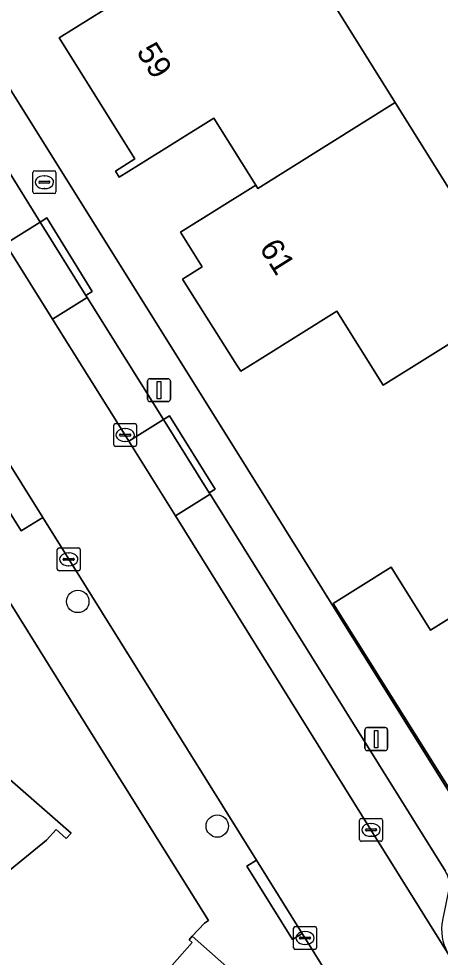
# Model space of a CAD drawing. Extents: x 158835 to 160077, y 386387 to 387778.
# Drawn here: x 159259.68 to 159278.07, y 386903.92 to 386944.89 of the extents above; entities that cross this region are included whole.
import ezdxf

# ---------------------------------------------------------------- set-up
doc = ezdxf.new("R2010")
doc.units = 0
for name, color, linetype in [('IMGEO_Boom', 7, 'Continuous'), ('IMGEO_Brandkraan', 7, 'Continuous'), ('IMGEO_Erf', 7, 'Continuous'), ('IMGEO_Kolk', 7, 'Continuous'), ('IMGEO_Lichtmast', 7, 'Continuous'), ('IMGEO_Muur', 7, 'Continuous'), ('IMGEO_Pand', 7, 'Continuous'), ('IMGEO_Pand_nummerreeks', 7, 'Continuous'), ('IMGEO_Parkeervlak_open', 7, 'Continuous'), ('IMGEO_Rijbaan_lokaal_open', 7, 'Continuous'), ('IMGEO_Voetpad_open', 7, 'Continuous')]:
    doc.layers.add(name, color=color, linetype=linetype)

msp = doc.modelspace()

# ---------------------------------------------------------------- linework, layer by layer
at = {"layer": 'IMGEO_Boom'}
for centre in [(159262.254, 386919.452), (159268.34, 386909.646)]:
    msp.add_circle(centre, 0.489, dxfattribs=at)
at = {"layer": 'IMGEO_Brandkraan'}
for p, q in [((159260.299, 386937.33), (159260.299, 386938.182)), ((159260.374, 386938.256), (159261.226, 386938.256)), ((159260.787, 386938.036), (159260.812, 386938.036)), ((159261.3, 386938.182), (159261.3, 386937.33)), ((159260.558, 386937.75), (159260.558, 386937.762)), ((159260.996, 386937.713), (159260.598, 386937.713)), ((159260.601, 386937.799), (159260.999, 386937.799)), ((159260.81, 386937.476), (159260.785, 386937.476)), ((159261.042, 386937.762), (159261.042, 386937.75)), ((159261.226, 386937.256), (159260.374, 386937.256))]:
    msp.add_line(p, q, dxfattribs=at)
for points in [[(159260.299, 386937.33), (159260.299, 386938.182)], [(159260.374, 386938.256), (159261.226, 386938.256)], [(159261.3, 386938.182), (159261.3, 386937.33)], [(159261.226, 386937.256), (159260.374, 386937.256)]]:
    msp.add_lwpolyline(points, dxfattribs=at)
for centre, radius, start, end in [((159260.376, 386938.18), 0.0765, 91.552, 178.448), ((159260.376, 386938.18), 0.0765, 91.552, 178.448), ((159261.224, 386938.18), 0.0765, 1.552, 88.448), ((159261.224, 386938.18), 0.0765, 1.552, 88.448), ((159260.598, 386937.759), 0.0403, 85.8775, 175.7526), ((159260.595, 386937.749), 0.0366, 178.938, 274.7102), ((159260.999, 386937.756), 0.043, 264.8664, 352.4533), ((159261.003, 386937.761), 0.0386, 1.7309, 96.639), ((159260.376, 386937.332), 0.0765, 181.552, 268.448), ((159260.376, 386937.332), 0.0765, 181.552, 268.448), ((159261.224, 386937.332), 0.0765, 271.552, 358.448), ((159261.224, 386937.332), 0.0765, 271.552, 358.448)]:
    msp.add_arc(centre, radius, start, end, dxfattribs=at)
for centre, major_axis, ratio, start_param, end_param in [((159260.786, 386937.756), (-0.387, 0.002), 0.722429, 4.712389, 7.853982), ((159260.811, 386937.756), (-0.39, 0.002), 0.717154, 1.570796, 4.712389)]:
    msp.add_ellipse(centre, major_axis=major_axis, ratio=ratio, start_param=start_param, end_param=end_param, dxfattribs=at)
at = {"layer": 'IMGEO_Erf'}
for points in [[(159231.551, 386986.255), (159234.22, 386981.98), (159243.007, 386967.906), (159269.667, 386925.206), (159275.29, 386916.2), (159281.43, 386906.366), (159281.531, 386906.228), (159281.643, 386906.1), (159281.767, 386905.982), (159281.9, 386905.876), (159282.043, 386905.783), (159282.193, 386905.702), (159282.35, 386905.635), (159282.513, 386905.582), (159282.682, 386905.544)], [(159270.805, 386949.721), (159276.102, 386941.24), (159281.5, 386932.598), (159275.572, 386928.895), (159273.559, 386932.118), (159270.217, 386930.031), (159269.363, 386929.508), (159269.196, 386929.772), (159266.827, 386933.518), (159267.687, 386934.062), (159266.74, 386935.572), (159270.02, 386937.621), (159268.188, 386940.554), (159264.908, 386938.505), (159264.062, 386937.972), (159263.893, 386938.244), (159264.739, 386938.775), (159261.439, 386944.056), (159264.719, 386946.106)], [(159250.309, 386879.575), (159252.121, 386882.09), (159254.029, 386880.721), (159252.222, 386878.203), (159261.297, 386871.692), (159264.16, 386875.708), (159253.134, 386883.625), (159256.2, 386887.125), (159263.288, 386882.016), (159266.18, 386886.027), (159259.472, 386890.864), (159265.812, 386898.129), (159263.427, 386900.23), (159267.244, 386904.559), (159267.108, 386904.678), (159267.248, 386904.836), (159267.781, 386905.402), (159267.952, 386905.515), (159262.274, 386914.62), (159257.972, 386921.518)], [(159279.018, 386910.377), (159273.393, 386919.361), (159275.926, 386920.947), (159277.645, 386918.202), (159283.167, 386921.647)], [(159245.823, 386903.008), (159243.006, 386905.468), (159246.984, 386910.024), (159249.801, 386907.563), (159251.956, 386910.047), (159249.142, 386912.511), (159253.125, 386917.06), (159261.959, 386909.328), (159261.749, 386909.097), (159261.316, 386909.492), (159260.895, 386909.03), (159258.189, 386906.835), (159254.923, 386903.111)]]:
    msp.add_lwpolyline(points, dxfattribs=at)
at = {"layer": 'IMGEO_Kolk'}
for p, q in [((159263.896, 386927.217), (159264.748, 386927.217)), ((159263.821, 386926.291), (159263.821, 386927.143)), ((159264.309, 386926.997), (159264.334, 386926.997)), ((159264.822, 386927.143), (159264.822, 386926.291)), ((159264.08, 386926.711), (159264.08, 386926.723)), ((159264.518, 386926.674), (159264.12, 386926.674)), ((159264.123, 386926.76), (159264.521, 386926.76)), ((159264.332, 386926.437), (159264.307, 386926.437)), ((159264.564, 386926.723), (159264.564, 386926.711)), ((159264.748, 386926.217), (159263.896, 386926.217)), ((159261.36, 386920.864), (159261.36, 386921.716)), ((159261.435, 386921.79), (159262.287, 386921.79)), ((159261.848, 386921.57), (159261.873, 386921.57)), ((159262.361, 386921.716), (159262.361, 386920.864)), ((159261.619, 386921.284), (159261.619, 386921.296)), ((159262.057, 386921.247), (159261.659, 386921.247)), ((159261.662, 386921.333), (159262.06, 386921.333)), ((159262.103, 386921.296), (159262.103, 386921.284)), ((159262.287, 386920.79), (159261.435, 386920.79)), ((159261.871, 386921.01), (159261.846, 386921.01)), ((159274.55, 386909.052), (159274.55, 386909.904)), ((159274.625, 386909.978), (159275.477, 386909.978)), ((159275.038, 386909.758), (159275.063, 386909.758)), ((159275.551, 386909.904), (159275.551, 386909.052)), ((159274.809, 386909.472), (159274.809, 386909.484)), ((159275.247, 386909.435), (159274.849, 386909.435)), ((159274.852, 386909.521), (159275.25, 386909.521)), ((159275.061, 386909.198), (159275.036, 386909.198)), ((159275.293, 386909.484), (159275.293, 386909.472)), ((159275.477, 386908.978), (159274.625, 386908.978)), ((159271.668, 386904.332), (159271.668, 386905.184)), ((159271.743, 386905.258), (159272.595, 386905.258)), ((159272.669, 386905.184), (159272.669, 386904.332)), ((159271.927, 386904.752), (159271.927, 386904.764)), ((159272.365, 386904.715), (159271.967, 386904.715)), ((159271.97, 386904.801), (159272.368, 386904.801)), ((159272.156, 386905.038), (159272.181, 386905.038)), ((159272.411, 386904.764), (159272.411, 386904.752)), ((159272.179, 386904.478), (159272.154, 386904.478)), ((159272.595, 386904.258), (159271.743, 386904.258))]:
    msp.add_line(p, q, dxfattribs=at)
for points in [[(159263.896, 386927.217), (159264.748, 386927.217)], [(159263.821, 386926.291), (159263.821, 386927.143)], [(159264.822, 386927.143), (159264.822, 386926.291)], [(159264.748, 386926.217), (159263.896, 386926.217)], [(159261.36, 386920.864), (159261.36, 386921.716)], [(159261.435, 386921.79), (159262.287, 386921.79)], [(159262.361, 386921.716), (159262.361, 386920.864)], [(159262.287, 386920.79), (159261.435, 386920.79)], [(159274.55, 386909.052), (159274.55, 386909.904)], [(159274.625, 386909.978), (159275.477, 386909.978)], [(159275.551, 386909.904), (159275.551, 386909.052)], [(159275.477, 386908.978), (159274.625, 386908.978)], [(159271.668, 386904.332), (159271.668, 386905.184)], [(159271.743, 386905.258), (159272.595, 386905.258)], [(159272.669, 386905.184), (159272.669, 386904.332)], [(159272.595, 386904.258), (159271.743, 386904.258)]]:
    msp.add_lwpolyline(points, dxfattribs=at)
for centre, radius, start, end in [((159263.898, 386927.141), 0.0765, 91.552, 178.448), ((159263.898, 386927.141), 0.0765, 91.552, 178.448), ((159264.746, 386927.141), 0.0765, 1.552, 88.448), ((159264.746, 386927.141), 0.0765, 1.552, 88.448), ((159264.12, 386926.72), 0.0403, 85.8775, 175.7526), ((159264.117, 386926.71), 0.0366, 178.938, 274.7102), ((159264.521, 386926.717), 0.043, 264.8664, 352.4533), ((159264.525, 386926.722), 0.0386, 1.7309, 96.639), ((159263.898, 386926.293), 0.0765, 181.552, 268.448), ((159263.898, 386926.293), 0.0765, 181.552, 268.448), ((159264.746, 386926.293), 0.0765, 271.552, 358.448), ((159264.746, 386926.293), 0.0765, 271.552, 358.448), ((159261.437, 386921.714), 0.0765, 91.552, 178.448), ((159261.437, 386921.714), 0.0765, 91.552, 178.448), ((159262.285, 386921.714), 0.0765, 1.552, 88.448), ((159262.285, 386921.714), 0.0765, 1.552, 88.448), ((159261.659, 386921.293), 0.0403, 85.8775, 175.7526), ((159261.656, 386921.283), 0.0366, 178.938, 274.7102), ((159262.06, 386921.29), 0.043, 264.8664, 352.4533), ((159262.064, 386921.295), 0.0386, 1.7309, 96.639), ((159261.437, 386920.866), 0.0765, 181.552, 268.448), ((159261.437, 386920.866), 0.0765, 181.552, 268.448), ((159262.285, 386920.866), 0.0765, 271.552, 358.448), ((159262.285, 386920.866), 0.0765, 271.552, 358.448), ((159274.627, 386909.902), 0.0765, 91.552, 178.448), ((159274.627, 386909.902), 0.0765, 91.552, 178.448), ((159275.475, 386909.902), 0.0765, 1.552, 88.448), ((159275.475, 386909.902), 0.0765, 1.552, 88.448), ((159274.849, 386909.481), 0.0403, 85.8775, 175.7526), ((159274.846, 386909.471), 0.0366, 178.938, 274.7102), ((159275.25, 386909.478), 0.043, 264.8664, 352.4533), ((159275.254, 386909.483), 0.0386, 1.7309, 96.639), ((159274.627, 386909.054), 0.0765, 181.552, 268.448), ((159274.627, 386909.054), 0.0765, 181.552, 268.448), ((159275.475, 386909.054), 0.0765, 271.552, 358.448), ((159275.475, 386909.054), 0.0765, 271.552, 358.448), ((159271.745, 386905.182), 0.0765, 91.552, 178.448), ((159271.745, 386905.182), 0.0765, 91.552, 178.448), ((159272.593, 386905.182), 0.0765, 1.552, 88.448), ((159272.593, 386905.182), 0.0765, 1.552, 88.448), ((159271.967, 386904.761), 0.0403, 85.8775, 175.7526), ((159271.964, 386904.751), 0.0366, 178.938, 274.7102), ((159272.368, 386904.758), 0.043, 264.8664, 352.4533), ((159272.372, 386904.763), 0.0386, 1.7309, 96.639), ((159271.745, 386904.334), 0.0765, 181.552, 268.448), ((159271.745, 386904.334), 0.0765, 181.552, 268.448), ((159272.593, 386904.334), 0.0765, 271.552, 358.448), ((159272.593, 386904.334), 0.0765, 271.552, 358.448)]:
    msp.add_arc(centre, radius, start, end, dxfattribs=at)
for centre, major_axis, ratio, start_param, end_param in [((159264.308, 386926.717), (-0.387, 0.002), 0.722429, 4.712389, 7.853982), ((159264.333, 386926.717), (-0.39, 0.002), 0.717154, 1.570796, 4.712389), ((159261.847, 386921.29), (-0.387, 0.002), 0.722429, 4.712389, 7.853982), ((159261.872, 386921.29), (-0.39, 0.002), 0.717154, 1.570796, 4.712389), ((159275.037, 386909.478), (-0.387, 0.002), 0.722429, 4.712389, 7.853982), ((159275.062, 386909.478), (-0.39, 0.002), 0.717154, 1.570796, 4.712389), ((159272.155, 386904.758), (-0.387, 0.002), 0.722429, 4.712389, 7.853982), ((159272.18, 386904.758), (-0.39, 0.002), 0.717154, 1.570796, 4.712389)]:
    msp.add_ellipse(centre, major_axis=major_axis, ratio=ratio, start_param=start_param, end_param=end_param, dxfattribs=at)
at = {"layer": 'IMGEO_Lichtmast'}
for p, q in [((159265.302, 386928.278), (159265.302, 386929.078)), ((159265.302, 386929.078), (159265.302, 386928.278)), ((159265.402, 386929.178), (159266.192, 386929.178)), ((159266.192, 386929.178), (159265.402, 386929.178)), ((159266.292, 386929.078), (159266.292, 386928.278)), ((159266.292, 386928.278), (159266.292, 386929.078)), ((159266.192, 386928.178), (159265.402, 386928.178)), ((159265.402, 386928.178), (159266.192, 386928.178)), ((159274.781, 386913.042), (159274.781, 386913.842)), ((159274.781, 386913.842), (159274.781, 386913.042)), ((159274.881, 386913.942), (159275.671, 386913.942)), ((159275.671, 386913.942), (159274.881, 386913.942)), ((159275.771, 386913.842), (159275.771, 386913.042)), ((159275.771, 386913.042), (159275.771, 386913.842)), ((159275.671, 386912.942), (159274.881, 386912.942)), ((159274.881, 386912.942), (159275.671, 386912.942))]:
    msp.add_line(p, q, dxfattribs=at)
for points in [[(159265.722, 386929.053), (159265.872, 386929.053), (159265.872, 386928.303), (159265.722, 386928.303), (159265.722, 386929.053)], [(159275.201, 386913.817), (159275.351, 386913.817), (159275.351, 386913.067), (159275.201, 386913.067), (159275.201, 386913.817)]]:
    msp.add_lwpolyline(points, dxfattribs=at)
for centre, start, end in [((159265.402, 386929.078), 90, 180), ((159265.402, 386929.078), 90, 180), ((159266.192, 386929.078), 0, 90), ((159266.192, 386929.078), 360, 90), ((159265.402, 386928.278), 180, 270), ((159265.402, 386928.278), 180, 270), ((159266.192, 386928.278), 270, 0), ((159266.192, 386928.278), 270, 0), ((159274.881, 386913.842), 90, 180), ((159274.881, 386913.842), 90, 180), ((159275.671, 386913.842), 0, 90), ((159275.671, 386913.842), 360, 90), ((159274.881, 386913.042), 180, 270), ((159274.881, 386913.042), 180, 270), ((159275.671, 386913.042), 270, 0), ((159275.671, 386913.042), 270, 0)]:
    msp.add_arc(centre, 0.1, start, end, dxfattribs=at)
at = {"layer": 'IMGEO_Muur'}
for points in [[(159269.667, 386925.206), (159275.29, 386916.2)], [(159262.274, 386914.62), (159267.952, 386905.515)]]:
    msp.add_lwpolyline(points, dxfattribs=at)
at = {"layer": 'IMGEO_Pand'}
for points in [[(159264.814, 386945.953), (159264.719, 386946.106), (159261.439, 386944.056), (159264.739, 386938.775), (159263.893, 386938.244), (159264.062, 386937.972), (159264.908, 386938.505), (159268.188, 386940.554), (159270.02, 386937.621), (159270.105, 386937.485), (159276.102, 386941.24), (159270.805, 386949.721)], [(159276.102, 386941.24), (159270.105, 386937.485), (159270.02, 386937.621), (159266.74, 386935.572), (159267.687, 386934.062), (159266.827, 386933.518), (159269.196, 386929.772), (159269.363, 386929.508), (159270.217, 386930.031), (159273.559, 386932.118), (159275.572, 386928.895), (159281.5, 386932.598)], [(159288.803, 386918.217), (159288.939, 386918.302), (159285.812, 386923.297), (159283.167, 386921.647), (159277.645, 386918.202), (159275.926, 386920.947), (159273.393, 386919.361), (159279.018, 386910.377), (159281.502, 386911.932), (159283.396, 386908.906), (159288.688, 386912.202), (159289.216, 386911.367), (159289.479, 386911.544), (159288.955, 386912.368), (159286.286, 386916.647)], [(159254.923, 386903.111), (159258.189, 386906.835), (159260.895, 386909.03), (159261.316, 386909.492), (159261.749, 386909.097), (159261.959, 386909.328), (159253.125, 386917.06), (159249.142, 386912.511), (159251.956, 386910.047), (159249.801, 386907.563)], [(159267.248, 386904.836), (159267.108, 386904.678), (159267.244, 386904.559), (159263.427, 386900.23), (159265.812, 386898.129), (159269.765, 386902.616)]]:
    msp.add_lwpolyline(points, close=True, dxfattribs=at)
at = {"layer": 'IMGEO_Parkeervlak_open'}
for points in [[(159257.366, 386941.241), (159255.843, 386940.29), (159259.101, 386935.072), (159260.615, 386936.017)], [(159260.615, 386936.017), (159259.101, 386935.072), (159261.156, 386931.78), (159262.661, 386932.72), (159262.603, 386932.813)], [(159262.661, 386932.72), (159261.156, 386931.78), (159264.317, 386926.716), (159264.481, 386926.453), (159265.997, 386927.397)], [(159265.997, 386927.397), (159264.481, 386926.453), (159266.513, 386923.188), (159268.029, 386924.132), (159267.988, 386924.198)], [(159268.029, 386924.132), (159266.513, 386923.188), (159275.045, 386909.477), (159278.442, 386904.025), (159278.4, 386904.098), (159278.318, 386904.264), (159278.25, 386904.437), (159278.199, 386904.615), (159278.163, 386904.798), (159278.144, 386904.982), (159278.142, 386905.168), (159278.156, 386905.353), (159278.187, 386905.536), (159278.453, 386906.896), (159278.465, 386906.991), (159278.469, 386907.087), (159278.465, 386907.183), (159278.451, 386907.278), (159278.43, 386907.371), (159278.4, 386907.462), (159278.362, 386907.55), (159278.316, 386907.635), (159278.292, 386907.673)]]:
    msp.add_lwpolyline(points, close=True, dxfattribs=at)
at = {"layer": 'IMGEO_Rijbaan_lokaal_open'}
for points in [[(159227.553, 386985.313), (159223.449, 386982.721), (159224.478, 386981.131), (159235.854, 386962.883), (159237.386, 386960.45), (159240.581, 386955.34), (159248.837, 386942.118), (159254.232, 386933.527), (159260.723, 386923.118), (159261.858, 386921.291), (159270.058, 386908.157), (159272.045, 386904.953), (159282.472, 386888.2), (159283.419, 386886.691), (159284.537, 386884.63)], [(159288.761, 386887.477), (159284.927, 386893.622), (159283.197, 386896.388), (159278.442, 386904.025), (159275.045, 386909.477), (159266.513, 386923.188), (159264.481, 386926.453), (159264.317, 386926.716), (159261.156, 386931.78), (159259.101, 386935.072), (159255.843, 386940.29), (159253.758, 386943.629), (159252.567, 386945.538), (159250.529, 386948.798), (159248.497, 386952.05), (159245.281, 386957.195), (159243.224, 386960.485), (159240.639, 386964.621), (159228.308, 386984.377)]]:
    msp.add_lwpolyline(points, dxfattribs=at)
at = {"layer": 'IMGEO_Voetpad_open'}
for points in [[(159269.667, 386925.206), (159243.007, 386967.906), (159234.22, 386981.98), (159231.551, 386986.255)], [(159282.472, 386888.2), (159272.045, 386904.953), (159271.621, 386904.69), (159269.634, 386907.894), (159270.058, 386908.157), (159261.858, 386921.291), (159260.723, 386923.118), (159259.79, 386922.536), (159253.299, 386932.945), (159254.232, 386933.527), (159248.837, 386942.118), (159240.581, 386955.34), (159240.158, 386955.075), (159236.963, 386960.185), (159237.386, 386960.45), (159235.854, 386962.883), (159224.478, 386981.131), (159223.449, 386982.721), (159223.266, 386983.004), (159223.156, 386983.138), (159223.042, 386983.268), (159218.721, 386980.624), (159218.693, 386980.571)], [(159221.474, 386979.958), (159222.954, 386977.516), (159223.124, 386977.244), (159223.673, 386976.361), (159227.951, 386969.495), (159228.453, 386968.689), (159233.986, 386959.896), (159234.626, 386958.869), (159236.282, 386956.214), (159237.938, 386953.56), (159245.033, 386942.24), (159250.995, 386932.728), (159257.972, 386921.518), (159262.274, 386914.62), (159267.952, 386905.515), (159267.781, 386905.402), (159267.248, 386904.836), (159269.765, 386902.616), (159272.047, 386898.934), (159274.852, 386894.442), (159281.467, 386883.527), (159282.706, 386881.503)], [(159252.048, 386949.747), (159255.271, 386944.573), (159255.544, 386944.744), (159255.583, 386944.682), (159257.583, 386941.48), (159257.629, 386941.405), (159257.366, 386941.241), (159260.615, 386936.017), (159260.9, 386936.194), (159262.888, 386932.99), (159262.603, 386932.813), (159262.661, 386932.72), (159265.997, 386927.397), (159266.252, 386927.556), (159268.243, 386924.357), (159267.988, 386924.198), (159268.029, 386924.132), (159278.292, 386907.673)], [(159281.43, 386906.366), (159275.29, 386916.2), (159269.667, 386925.206)]]:
    msp.add_lwpolyline(points, dxfattribs=at)
for points in [[(159260.9, 386936.194), (159260.615, 386936.017), (159262.603, 386932.813), (159262.888, 386932.99)], [(159260.723, 386923.118), (159254.232, 386933.527), (159253.299, 386932.945), (159259.79, 386922.536)], [(159266.252, 386927.556), (159265.997, 386927.397), (159267.988, 386924.198), (159268.243, 386924.357)], [(159270.058, 386908.157), (159269.634, 386907.894), (159271.621, 386904.69), (159272.045, 386904.953)]]:
    msp.add_lwpolyline(points, close=True, dxfattribs=at)

# ---------------------------------------------------------------- texts
at = {"layer": 'IMGEO_Pand_nummerreeks'}
for s, rotation, p in [('59', 302.0005, (159264.788, 386943.451)), ('61', 302.1083, (159270.15, 386934.88))]:
    msp.add_text(s, height=1, rotation=rotation, dxfattribs=at).set_placement(p)

doc.saveas('drawing.dxf')
